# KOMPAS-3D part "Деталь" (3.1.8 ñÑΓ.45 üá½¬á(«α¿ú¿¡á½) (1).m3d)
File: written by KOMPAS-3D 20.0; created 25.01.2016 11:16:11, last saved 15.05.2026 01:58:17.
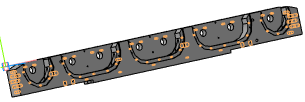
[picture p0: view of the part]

Document properties: Полное имя файла: E:\test_kompas\all_v18\3.1.8 дет.45 Балка(оригинал) (1).m3d

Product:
- Part/product: Деталь
    Масса: 261.985
  - Body: Тело 1

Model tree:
1. Эскиз:1
2. Операция выдавливания:1
     Расстояние 1 = 115
3. Эскиз:9  (with: Операция выдавливания:1)
4. Вырезать элемент выдавливания:13
     Расстояние 1 = 115
5. Эскиз:19  (with: Операция выдавливания:1)
6. Вырезать элемент выдавливания:14
     Расстояние 1 = 231
7. Эскиз:20  (with: Операция выдавливания:1)
8. Эскиз:21  (with: Операция выдавливания:1)
9. Вырезать элемент выдавливания:15
     Расстояние 1 = 75
10. Вырезать элемент выдавливания:16
     Расстояние 1 = 10
11. Эскиз:22  (with: Операция выдавливания:1, Вырезать элемент выдавливания:14)
12. Вырезать элемент выдавливания:17
     Расстояние 1 = 30
13. Эскиз:23  (with: Операция выдавливания:1)
14. Вырезать элемент выдавливания:18
     Расстояние 1 = 30
15. Условное изображение резьбы:1  (with: Вырезать элемент выдавливания:17)
     Длина резьбы = 30; Шаг резьбы = 2; Номинальный диаметр резьбы = 20.0651
16. Условное изображение резьбы:2  (with: Вырезать элемент выдавливания:17)
     Длина резьбы = 30; Шаг резьбы = 2; Номинальный диаметр резьбы = 20.0651
17. Условное изображение резьбы:3  (with: Вырезать элемент выдавливания:18)
     Длина резьбы = 30; Шаг резьбы = 2; Номинальный диаметр резьбы = 20.0651
18. Условное изображение резьбы:4  (with: Вырезать элемент выдавливания:18)
     Длина резьбы = 30; Шаг резьбы = 2; Номинальный диаметр резьбы = 20.0651
19. Эскиз:24  (with: Операция выдавливания:1)
20. Вырезать элемент выдавливания:19
     Расстояние 1 = 75
21. Эскиз:25  (with: Операция выдавливания:1)
22. Вырезать элемент выдавливания:20
     Расстояние 1 = 35
23. Условное изображение резьбы:5  (with: Вырезать элемент выдавливания:20)
     Длина резьбы = 35; Шаг резьбы = 1.5; Номинальный диаметр резьбы = 20.0538
24. Условное изображение резьбы:6  (with: Вырезать элемент выдавливания:20)
     Длина резьбы = 35; Шаг резьбы = 1.5; Номинальный диаметр резьбы = 20.0538
25. Условное изображение резьбы:7  (with: Вырезать элемент выдавливания:20)
     Длина резьбы = 35; Шаг резьбы = 1.5; Номинальный диаметр резьбы = 20.0538
26. Условное изображение резьбы:8  (with: Вырезать элемент выдавливания:20)
     Длина резьбы = 35; Шаг резьбы = 1.5; Номинальный диаметр резьбы = 20.0538
27. Условное изображение резьбы:9  (with: Вырезать элемент выдавливания:20)
     Длина резьбы = 35; Шаг резьбы = 1; Номинальный диаметр резьбы = 19.5125
28. Условное изображение резьбы:10  (with: Вырезать элемент выдавливания:20)
     Длина резьбы = 35; Шаг резьбы = 1; Номинальный диаметр резьбы = 19.5125
29. Эскиз:26  (with: Операция выдавливания:1, Вырезать элемент выдавливания:13)
30. Вырезать элемент выдавливания:21
     Расстояние 1 = 35
31. Условное изображение резьбы:11  (with: Вырезать элемент выдавливания:21)
     Длина резьбы = 35; Шаг резьбы = 1.5; Номинальный диаметр резьбы = 20.0538
32. Условное изображение резьбы:12  (with: Вырезать элемент выдавливания:21)
     Длина резьбы = 35; Шаг резьбы = 1.5; Номинальный диаметр резьбы = 20.0538
33. Условное изображение резьбы:13  (with: Вырезать элемент выдавливания:21)
     Длина резьбы = 35; Шаг резьбы = 1.5; Номинальный диаметр резьбы = 20.0538
34. Условное изображение резьбы:14  (with: Вырезать элемент выдавливания:21)
     Длина резьбы = 35; Шаг резьбы = 1.5; Номинальный диаметр резьбы = 20.0538
35. Условное изображение резьбы:15  (with: Вырезать элемент выдавливания:21)
     Длина резьбы = 35; Шаг резьбы = 1.5; Номинальный диаметр резьбы = 20.0538
36. Условное изображение резьбы:16  (with: Вырезать элемент выдавливания:21)
     Длина резьбы = 35; Шаг резьбы = 1.5; Номинальный диаметр резьбы = 20.0538
37. Эскиз:27  (with: Операция выдавливания:1, Вырезать элемент выдавливания:15)
38. Эскиз:28  (with: Операция выдавливания:1)
39. Вырезать элемент выдавливания:22
     Расстояние 1 = 115
40. Эскиз:29  (with: Вырезать элемент выдавливания:16)
41. Вырезать элемент выдавливания:23
     Расстояние 1 = 13
42. Эскиз:30  (with: Вырезать элемент выдавливания:16)
43. Вырезать элемент выдавливания:24
     Расстояние 1 = 13
44. Условное изображение резьбы:17  (with: Вырезать элемент выдавливания:23)
     Длина резьбы = 13; Шаг резьбы = 1; Номинальный диаметр резьбы = 9.51253
45. Условное изображение резьбы:18  (with: Вырезать элемент выдавливания:23)
     Длина резьбы = 13; Шаг резьбы = 1; Номинальный диаметр резьбы = 9.51253
46. Условное изображение резьбы:19  (with: Вырезать элемент выдавливания:23)
     Длина резьбы = 13; Шаг резьбы = 1; Номинальный диаметр резьбы = 9.51253
47. Условное изображение резьбы:20  (with: Вырезать элемент выдавливания:23)
     Длина резьбы = 13; Шаг резьбы = 1; Номинальный диаметр резьбы = 9.51253
48. Условное изображение резьбы:21  (with: Вырезать элемент выдавливания:23)
     Длина резьбы = 13; Шаг резьбы = 1; Номинальный диаметр резьбы = 9.51253
49. Условное изображение резьбы:22  (with: Вырезать элемент выдавливания:24)
     Длина резьбы = 13; Шаг резьбы = 1; Номинальный диаметр резьбы = 9.51253
50. Условное изображение резьбы:23  (with: Вырезать элемент выдавливания:24)
     Длина резьбы = 13; Шаг резьбы = 1; Номинальный диаметр резьбы = 9.51253
51. Условное изображение резьбы:24  (with: Вырезать элемент выдавливания:24)
     Длина резьбы = 13; Шаг резьбы = 1; Номинальный диаметр резьбы = 9.51253
52. Условное изображение резьбы:25  (with: Вырезать элемент выдавливания:24)
     Длина резьбы = 13; Шаг резьбы = 1; Номинальный диаметр резьбы = 9.51253
53. Условное изображение резьбы:26  (with: Вырезать элемент выдавливания:24)
     Длина резьбы = 13; Шаг резьбы = 1; Номинальный диаметр резьбы = 9.51253
54. Эскиз:31  (with: Вырезать элемент выдавливания:16, Вырезать элемент выдавливания:19)
55. Вырезать элемент выдавливания:25
     Расстояние 1 = 13
56. Условное изображение резьбы:27  (with: Вырезать элемент выдавливания:25)
     Длина резьбы = 13; Шаг резьбы = 1; Номинальный диаметр резьбы = 9.51253
57. Условное изображение резьбы:28  (with: Вырезать элемент выдавливания:25)
     Длина резьбы = 13; Шаг резьбы = 1; Номинальный диаметр резьбы = 9.51253
58. Условное изображение резьбы:29  (with: Вырезать элемент выдавливания:25)
     Длина резьбы = 13; Шаг резьбы = 1; Номинальный диаметр резьбы = 9.51253
59. Условное изображение резьбы:30  (with: Вырезать элемент выдавливания:25)
     Длина резьбы = 13; Шаг резьбы = 1; Номинальный диаметр резьбы = 9.51253
60. Условное изображение резьбы:31  (with: Вырезать элемент выдавливания:25)
     Длина резьбы = 13; Шаг резьбы = 1; Номинальный диаметр резьбы = 9.51253
61. Условное изображение резьбы:32  (with: Вырезать элемент выдавливания:25)
     Длина резьбы = 13; Шаг резьбы = 1; Номинальный диаметр резьбы = 9.51253
62. Условное изображение резьбы:33  (with: Вырезать элемент выдавливания:25)
     Длина резьбы = 13; Шаг резьбы = 1; Номинальный диаметр резьбы = 9.51253
63. Эскиз:32  (with: Вырезать элемент выдавливания:16)
64. Вырезать элемент выдавливания:26
     Расстояние 1 = 13
65. Условное изображение резьбы:34  (with: Вырезать элемент выдавливания:26)
     Длина резьбы = 13; Шаг резьбы = 1; Номинальный диаметр резьбы = 9.51253
66. Условное изображение резьбы:35  (with: Вырезать элемент выдавливания:26)
     Длина резьбы = 13; Шаг резьбы = 1; Номинальный диаметр резьбы = 9.51253
67. Условное изображение резьбы:36  (with: Вырезать элемент выдавливания:26)
     Длина резьбы = 13; Шаг резьбы = 1; Номинальный диаметр резьбы = 9.51253
68. Условное изображение резьбы:37  (with: Вырезать элемент выдавливания:26)
     Длина резьбы = 13; Шаг резьбы = 1; Номинальный диаметр резьбы = 9.51253
69. Условное изображение резьбы:38  (with: Вырезать элемент выдавливания:26)
     Длина резьбы = 13; Шаг резьбы = 1; Номинальный диаметр резьбы = 9.51253
70. Условное изображение резьбы:39  (with: Вырезать элемент выдавливания:26)
     Длина резьбы = 13; Шаг резьбы = 1; Номинальный диаметр резьбы = 9.51253
71. Условное изображение резьбы:40  (with: Вырезать элемент выдавливания:26)
     Длина резьбы = 13; Шаг резьбы = 1; Номинальный диаметр резьбы = 9.51253
72. Эскиз:33  (with: Вырезать элемент выдавливания:16)
73. Вырезать элемент выдавливания:27
     Расстояние 1 = 13
74. Условное изображение резьбы:41  (with: Вырезать элемент выдавливания:27)
     Длина резьбы = 13; Шаг резьбы = 1; Номинальный диаметр резьбы = 9.51253
75. Условное изображение резьбы:42  (with: Вырезать элемент выдавливания:27)
     Длина резьбы = 13; Шаг резьбы = 1; Номинальный диаметр резьбы = 9.51253
76. Условное изображение резьбы:43  (with: Вырезать элемент выдавливания:27)
     Длина резьбы = 13; Шаг резьбы = 1; Номинальный диаметр резьбы = 9.51253
77. Условное изображение резьбы:44  (with: Вырезать элемент выдавливания:27)
     Длина резьбы = 13; Шаг резьбы = 1; Номинальный диаметр резьбы = 9.51253
78. Условное изображение резьбы:45  (with: Вырезать элемент выдавливания:27)
     Длина резьбы = 13; Шаг резьбы = 1; Номинальный диаметр резьбы = 9.51253
79. Условное изображение резьбы:46  (with: Вырезать элемент выдавливания:27)
     Длина резьбы = 13; Шаг резьбы = 1; Номинальный диаметр резьбы = 9.51253
80. Условное изображение резьбы:47  (with: Вырезать элемент выдавливания:27)
     Длина резьбы = 13; Шаг резьбы = 1; Номинальный диаметр резьбы = 9.51253
81. Эскиз:34  (with: Операция выдавливания:1)
82. Эскиз:35  (with: Операция выдавливания:1, Вырезать элемент выдавливания:17)
83. Вырезать элемент выдавливания:28
     Расстояние 1 = 94
84. Эскиз:36  (with: Операция выдавливания:1)
85. Вырезать элемент выдавливания:29
     Расстояние 1 = 21
86. Эскиз:37  (with: Вырезать элемент выдавливания:15)
87. Вырезать элемент выдавливания:30
     Расстояние 1 = 40
88. Эскиз:38  (with: Операция выдавливания:1)
89. Вырезать элемент выдавливания:31
     Расстояние 1 = 10
90. Эскиз:39  (with: Операция выдавливания:1)
91. Вырезать элемент выдавливания:32
     Расстояние 1 = 50
92. Условное изображение резьбы:48  (with: Вырезать элемент выдавливания:32)
     Длина резьбы = 50; Шаг резьбы = 1; Номинальный диаметр резьбы = 18.0325
93. Условное изображение резьбы:49  (with: Вырезать элемент выдавливания:32)
     Длина резьбы = 50; Шаг резьбы = 1; Номинальный диаметр резьбы = 18.0325
94. Условное изображение резьбы:50  (with: Вырезать элемент выдавливания:32)
     Длина резьбы = 50; Шаг резьбы = 1; Номинальный диаметр резьбы = 18.0325
95. Условное изображение резьбы:51  (with: Вырезать элемент выдавливания:32)
     Длина резьбы = 50; Шаг резьбы = 1; Номинальный диаметр резьбы = 18.0325
96. Эскиз:40  (with: Операция выдавливания:1, Вырезать элемент выдавливания:13, Вырезать элемент выдавливания:22, Вырезать элемент выдавливания:29)
97. Вырезать элемент выдавливания:33
     Расстояние 1 = 70
98. Условное изображение резьбы:52  (with: Вырезать элемент выдавливания:33)
     Длина резьбы = 70; Шаг резьбы = 1; Номинальный диаметр резьбы = 28.0325
99. Условное изображение резьбы:53  (with: Вырезать элемент выдавливания:33)
     Длина резьбы = 70; Шаг резьбы = 1; Номинальный диаметр резьбы = 28.0325
100. Эскиз:41  (with: Операция выдавливания:1)
101. Вырезать элемент выдавливания:34
     Расстояние 1 = 30
102. Условное изображение резьбы:54  (with: Вырезать элемент выдавливания:34)
     Длина резьбы = 30; Шаг резьбы = 1; Номинальный диаметр резьбы = 8.03253
103. Условное изображение резьбы:55  (with: Вырезать элемент выдавливания:34)
     Длина резьбы = 30; Шаг резьбы = 1; Номинальный диаметр резьбы = 8.03253
104. Условное изображение резьбы:56  (with: Вырезать элемент выдавливания:34)
     Длина резьбы = 30; Шаг резьбы = 1; Номинальный диаметр резьбы = 8.03253
105. Условное изображение резьбы:57  (with: Вырезать элемент выдавливания:34)
     Длина резьбы = 30; Шаг резьбы = 1; Номинальный диаметр резьбы = 8.03253
106. Условное изображение резьбы:58  (with: Вырезать элемент выдавливания:34)
     Длина резьбы = 30; Шаг резьбы = 1; Номинальный диаметр резьбы = 8.03253
107. Вырезать элемент выдавливания:35
     Расстояние 1 = 10
108. Эскиз:42  (with: Операция выдавливания:1, Вырезать элемент выдавливания:33)
109. Вырезать элемент выдавливания:36
     Расстояние 1 = 55
110. Условное изображение резьбы:59  (with: Вырезать элемент выдавливания:36)
     Длина резьбы = 55; Шаг резьбы = 1; Номинальный диаметр резьбы = 16.0325
111. Эскиз:43  (with: Операция выдавливания:1, Вырезать элемент выдавливания:22)
112. Вырезать элемент выдавливания:37
     Расстояние 1 = 30
113. Условное изображение резьбы:60  (with: Вырезать элемент выдавливания:37)
     Длина резьбы = 30; Шаг резьбы = 1; Номинальный диаметр резьбы = 11.0325
114. Условное изображение резьбы:61  (with: Вырезать элемент выдавливания:37)
     Длина резьбы = 30; Шаг резьбы = 1; Номинальный диаметр резьбы = 11.0325
115. Условное изображение резьбы:62  (with: Вырезать элемент выдавливания:37)
     Длина резьбы = 30; Шаг резьбы = 1; Номинальный диаметр резьбы = 11.0325
116. Условное изображение резьбы:63  (with: Вырезать элемент выдавливания:37)
     Длина резьбы = 30; Шаг резьбы = 1; Номинальный диаметр резьбы = 11.0325
117. Условное изображение резьбы:64  (with: Вырезать элемент выдавливания:37)
     Длина резьбы = 30; Шаг резьбы = 1; Номинальный диаметр резьбы = 11.0325
118. Условное изображение резьбы:65  (with: Вырезать элемент выдавливания:37)
     Длина резьбы = 30; Шаг резьбы = 1; Номинальный диаметр резьбы = 11.0325
119. Условное изображение резьбы:66  (with: Вырезать элемент выдавливания:37)
     Длина резьбы = 30; Шаг резьбы = 1; Номинальный диаметр резьбы = 11.0325
120. Условное изображение резьбы:67  (with: Вырезать элемент выдавливания:37)
     Длина резьбы = 30; Шаг резьбы = 1; Номинальный диаметр резьбы = 11.0325
121. Условное изображение резьбы:68  (with: Вырезать элемент выдавливания:37)
     Длина резьбы = 30; Шаг резьбы = 1; Номинальный диаметр резьбы = 11.0325
122. Условное изображение резьбы:69  (with: Вырезать элемент выдавливания:37)
     Длина резьбы = 30; Шаг резьбы = 1; Номинальный диаметр резьбы = 11.0325
123. Условное изображение резьбы:70  (with: Вырезать элемент выдавливания:37)
     Длина резьбы = 30; Шаг резьбы = 1; Номинальный диаметр резьбы = 11.0325
124. Условное изображение резьбы:71  (with: Вырезать элемент выдавливания:37)
     Длина резьбы = 30; Шаг резьбы = 1; Номинальный диаметр резьбы = 11.0325
125. Условное изображение резьбы:72  (with: Вырезать элемент выдавливания:37)
     Длина резьбы = 30; Шаг резьбы = 1; Номинальный диаметр резьбы = 11.0325
126. Условное изображение резьбы:73  (with: Вырезать элемент выдавливания:37)
     Длина резьбы = 30; Шаг резьбы = 1; Номинальный диаметр резьбы = 11.0325
127. Условное изображение резьбы:74  (with: Вырезать элемент выдавливания:37)
     Длина резьбы = 30; Шаг резьбы = 1; Номинальный диаметр резьбы = 11.0325
128. Условное изображение резьбы:75  (with: Вырезать элемент выдавливания:37)  (labels: 4061045924-6285-0-0|0)
     Длина резьбы = 30; Шаг резьбы = 1; Номинальный диаметр резьбы = 11.0325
